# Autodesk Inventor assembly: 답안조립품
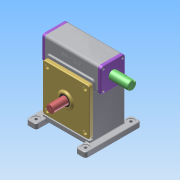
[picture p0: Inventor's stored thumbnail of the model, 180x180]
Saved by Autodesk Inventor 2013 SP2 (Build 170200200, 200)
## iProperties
Created: 2025-06
Part Number: 답안조립품
Document SubType Name: Assembly
Designer: a
Author: a
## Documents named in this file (11)
- C:\Users\a\Desktop\750603V1004\답안조립품.iam
- C:\Users\a\Desktop\750603V1004\본체.ipt
- C:\Users\a\Desktop\750603V1004\웜 휠.ipt
- C:\Users\a\Desktop\750603V1004\깊은 홈 볼 베어링 6206.ipt
- C:\Users\a\Desktop\750603V1004\오일 실 30 42 7.ipt
- C:\Users\a\Desktop\750603V1004\뒷커버.ipt
- C:\Users\a\Desktop\750603V1004\앞커버.ipt
- C:\Users\a\Desktop\750603V1004\웜 휠 커버.ipt
- C:\Users\a\Desktop\750603V1004\웜 샤프트.ipt
- C:\Users\a\Desktop\750603V1004\깊은 홈 볼 베어링 6209.ipt
- C:\Users\a\Desktop\750603V1004\6각 구멍붙이 볼트 M6x12.ipt
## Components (8 placed, 1 different names)
1. 6각 구멍붙이 볼트 M6x12:1
2. 6각 구멍붙이 볼트 M6x12:3
3. 6각 구멍붙이 볼트 M6x12:4
4. 6각 구멍붙이 볼트 M6x12:5
5. 6각 구멍붙이 볼트 M6x12:6
6. 6각 구멍붙이 볼트 M6x12:7
7. 6각 구멍붙이 볼트 M6x12:8
8. 6각 구멍붙이 볼트 M6x12:9
